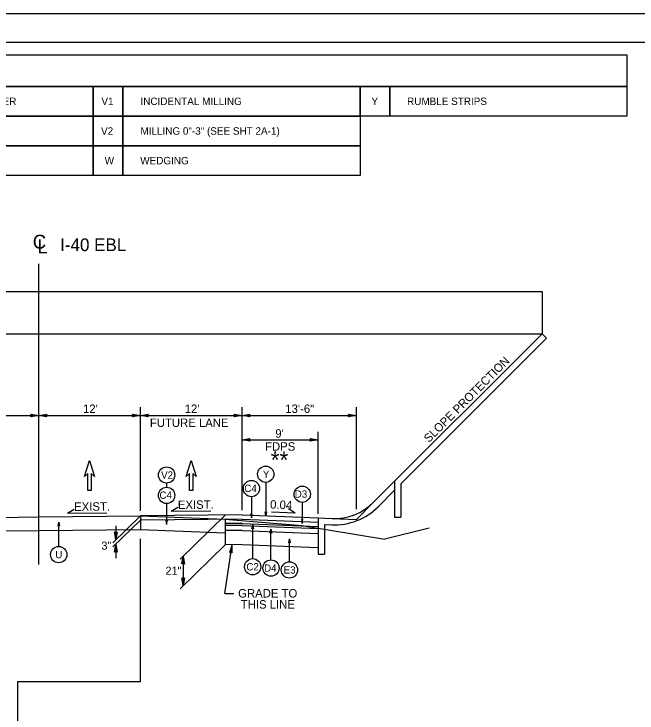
# Model space of a CAD drawing. Extents: x 1553884 to 1554215, y 810431 to 810779.
# Drawn here: x 1554061 to 1554134.5, y 810513.5 to 810596 of the extents above; entities that cross this region are included whole.
import ezdxf

# ---------------------------------------------------------------- set-up
doc = ezdxf.new("R2010")
doc.units = 0
for name, color, linetype in [('Old_Level_15', 7, 'Continuous'), ('Old_Level_2', 7, 'Continuous'), ('Old_Level_20', 7, 'Continuous'), ('P_RDY_Bridge_Abutment', 7, 'Continuous'), ('Prop Dimension', 7, 'Continuous'), ('Prop Hatching', 7, 'Continuous'), ('Prop Lane Arrow CELL', 7, 'Continuous'), ('Prop Shade Light', 7, 'Continuous'), ('Typical Arrow Superelevation CELL', 7, 'Continuous'), ('Typical Detail Pavement Repair CELL', 7, 'Continuous'), ('Typical Shoulder Slope CELL', 7, 'Continuous'), ('Typical Text Centerline CELL', 7, 'Continuous'), ('Typical Text ID Circle CELL', 7, 'Continuous')]:
    doc.layers.add(name, color=color, linetype=linetype)

msp = doc.modelspace()

# ---------------------------------------------------------------- linework, layer by layer
at = {"layer": 'Old_Level_15'}
for points in [[(1554062.95, 810548.722), (1554063.887, 810548.561), (1554062.945, 810548.394), (1554063.064, 810548.561)], [(1554064.825, 810548.4), (1554063.887, 810548.561), (1554064.83, 810548.728), (1554064.71, 810548.561)], [(1554074.95, 810548.722), (1554075.887, 810548.561), (1554074.945, 810548.394), (1554075.064, 810548.561)], [(1554076.825, 810548.4), (1554075.887, 810548.561), (1554076.83, 810548.728), (1554076.71, 810548.561)], [(1554086.95, 810548.722), (1554087.887, 810548.561), (1554086.945, 810548.394), (1554087.064, 810548.561)], [(1554088.825, 810548.4), (1554087.887, 810548.561), (1554088.83, 810548.728), (1554088.71, 810548.561)], [(1554100.45, 810548.722), (1554101.387, 810548.561), (1554100.445, 810548.394), (1554100.564, 810548.561)], [(1554088.825, 810545.538), (1554087.887, 810545.7), (1554088.83, 810545.866), (1554088.71, 810545.7)], [(1554095.95, 810545.861), (1554096.887, 810545.7), (1554095.945, 810545.533), (1554096.064, 810545.7)], [(1554090.767, 810537.19), (1554090.686, 810536.722), (1554090.603, 810537.193), (1554090.686, 810537.133)], [(1554088.925, 810536.968), (1554089.006, 810536.5), (1554089.089, 810536.971), (1554089.006, 810536.911)], [(1554094.916, 810536.298), (1554094.997, 810535.83), (1554095.08, 810536.301), (1554094.997, 810536.241)], [(1554066.169, 810535.51), (1554066.25, 810535.978), (1554066.333, 810535.507), (1554066.25, 810535.567)], [(1554078.908, 810536.163), (1554078.989, 810535.694), (1554079.072, 810536.165), (1554078.989, 810536.106)], [(1554089.065, 810535.208), (1554089.146, 810535.677), (1554089.229, 810535.206), (1554089.146, 810535.266)], [(1554073.15, 810534.815), (1554072.988, 810533.877), (1554072.822, 810534.82), (1554072.988, 810534.7)], [(1554091.229, 810534.689), (1554091.309, 810535.158), (1554091.393, 810534.687), (1554091.309, 810534.747)], [(1554093.409, 810533.556), (1554093.49, 810534.025), (1554093.573, 810533.554), (1554093.49, 810533.614)], [(1554072.827, 810532.44), (1554072.988, 810533.377), (1554073.155, 810532.435), (1554072.988, 810532.554)], [(1554086.738, 810532.371), (1554086.719, 810533.322), (1554086.413, 810532.415), (1554086.596, 810532.509)], [(1554080.787, 810531.044), (1554080.948, 810531.982), (1554081.115, 810531.039), (1554080.948, 810531.159)], [(1554081.11, 810529.419), (1554080.948, 810528.482), (1554080.782, 810529.424), (1554080.948, 810529.304)]]:
    msp.add_lwpolyline(points, close=True, dxfattribs=at)
at = {"layer": 'Old_Level_2'}
msp.add_line((1554154.325, 810592.576), (1553906.825, 810592.576), dxfattribs=at)
at = {"layer": 'Old_Level_20'}
for p, q in [((1554051.887, 810536.474), (1554063.887, 810536.594)), ((1554063.887, 810536.594), (1554075.887, 810536.714)), ((1554075.887, 810536.714), (1554072.651, 810533.548)), ((1554075.887, 810536.214), (1554072.651, 810533.048)), ((1554075.887, 810536.714), (1554085.887, 810536.314)), ((1554075.887, 810536.714), (1554075.887, 810535.129)), ((1554085.887, 810536.814), (1554080.57, 810531.611)), ((1554085.887, 810536.314), (1554085.887, 810534.729)), ((1554085.887, 810536.314), (1554094.933, 810535.59)), ((1554072.988, 810535.544), (1554072.988, 810533.877)), ((1554094.933, 810535.59), (1554104.761, 810533.952)), ((1554051.887, 810534.889), (1554063.887, 810535.009)), ((1554063.887, 810535.009), (1554075.887, 810535.129)), ((1554075.887, 810535.129), (1554085.887, 810534.729)), ((1554109.972, 810535.255), (1554104.761, 810533.952)), ((1554072.988, 810533.377), (1554072.988, 810531.711)), ((1554085.887, 810533.314), (1554080.57, 810528.111)), ((1554080.948, 810531.982), (1554080.948, 810528.482))]:
    msp.add_line(p, q, dxfattribs=at)
at = {"layer": 'P_RDY_Bridge_Abutment'}
for p, q in [((1553919.386, 810563.217), (1554123.308, 810563.217)), ((1554123.308, 810563.217), (1554123.308, 810558.217)), ((1553919.386, 810558.217), (1554123.308, 810558.217)), ((1554103.421, 810538.329), (1554123.308, 810558.217)), ((1554106.637, 810540.485), (1554123.838, 810557.686)), ((1554123.308, 810558.217), (1554123.838, 810557.686)), ((1554105.887, 810540.796), (1554105.887, 810536.554)), ((1554106.637, 810540.485), (1554106.637, 810536.554)), ((1554103.951, 810537.799), (1554105.887, 810539.735)), ((1554101.387, 810536.296), (1554103.421, 810538.329)), ((1554096.887, 810536.474), (1554098.514, 810536.409)), ((1554096.887, 810536.474), (1554096.887, 810532.218)), ((1554098.514, 810536.409), (1554101.387, 810536.296)), ((1554105.887, 810536.554), (1554106.637, 810536.554)), ((1554097.637, 810535.693), (1554098.484, 810535.66)), ((1554097.637, 810535.693), (1554097.637, 810532.218)), ((1554096.887, 810532.218), (1554097.637, 810532.218))]:
    msp.add_line(p, q, dxfattribs=at)
for radius in [6.572, 7.322]:
    msp.add_arc((1554098.773, 810542.976), radius, 267.73793, 315, dxfattribs=at)
at = {"layer": 'Prop Dimension'}
for points in [[(1553912.825, 810591.115), (1554133.325, 810591.115), (1554133.325, 810587.396), (1553912.825, 810587.396)], [(1554042.325, 810587.396), (1554070.325, 810587.396), (1554070.325, 810583.896), (1554042.325, 810583.896)], [(1554070.325, 810587.396), (1554073.825, 810587.396), (1554073.825, 810583.896), (1554070.325, 810583.896)], [(1554070.325, 810587.396), (1554073.825, 810587.396), (1554073.825, 810583.896), (1554070.325, 810583.896)], [(1554073.825, 810587.396), (1554101.825, 810587.396), (1554101.825, 810583.896), (1554073.825, 810583.896)], [(1554101.825, 810587.396), (1554105.325, 810587.396), (1554105.325, 810583.896), (1554101.825, 810583.896)], [(1554101.825, 810587.396), (1554105.325, 810587.396), (1554105.325, 810583.896), (1554101.825, 810583.896)], [(1554105.325, 810587.396), (1554133.325, 810587.396), (1554133.325, 810583.896), (1554105.325, 810583.896)], [(1554042.325, 810583.896), (1554070.325, 810583.896), (1554070.325, 810580.396), (1554042.325, 810580.396)], [(1554070.325, 810583.896), (1554073.825, 810583.896), (1554073.825, 810580.396), (1554070.325, 810580.396)], [(1554073.825, 810583.896), (1554101.825, 810583.896), (1554101.825, 810580.396), (1554073.825, 810580.396)], [(1554042.325, 810580.396), (1554070.325, 810580.396), (1554070.325, 810576.896), (1554042.325, 810576.896)], [(1554070.325, 810580.396), (1554073.825, 810580.396), (1554073.825, 810576.896), (1554070.325, 810576.896)], [(1554073.825, 810580.396), (1554101.825, 810580.396), (1554101.825, 810576.896), (1554073.825, 810576.896)]]:
    msp.add_lwpolyline(points, close=True, dxfattribs=at)
at = {"layer": 'Prop Hatching'}
for p, q in [((1554063.887, 810530.987), (1554063.887, 810566.46)), ((1554075.887, 810517.168), (1554075.887, 810533.991)), ((1554061.417, 810502.52), (1554061.417, 810517.168)), ((1554061.417, 810517.168), (1554075.887, 810517.168))]:
    msp.add_line(p, q, dxfattribs=at)
for points in [[(1554070.481, 810541.354), (1554070.075, 810541.729), (1554070.075, 810539.729), (1554069.7, 810539.729), (1554069.7, 810541.729), (1554069.294, 810541.354), (1554069.887, 810543.26)], [(1554082.481, 810541.354), (1554082.075, 810541.729), (1554082.075, 810539.729), (1554081.7, 810539.729), (1554081.7, 810541.729), (1554081.294, 810541.354), (1554081.887, 810543.26)]]:
    msp.add_lwpolyline(points, close=True, dxfattribs=at)
at = {"layer": 'Prop Lane Arrow CELL'}
msp.add_line((1554156.35, 810595.951), (1553901.353, 810595.951), dxfattribs=at)
at = {"layer": 'Prop Shade Light'}
for p, q in [((1554087.887, 810536.834), (1554075.887, 810536.714)), ((1554087.887, 810536.334), (1554075.887, 810536.214)), ((1554087.887, 810536.834), (1554096.887, 810536.474)), ((1554087.887, 810536.334), (1554096.887, 810535.974)), ((1554087.887, 810535.834), (1554085.887, 810535.814)), ((1554087.887, 810535.584), (1554085.887, 810535.564)), ((1554087.887, 810535.834), (1554096.887, 810535.474)), ((1554087.887, 810535.584), (1554096.887, 810535.224)), ((1554087.887, 810535), (1554085.887, 810534.98)), ((1554085.887, 810534.729), (1554085.887, 810533.314)), ((1554087.887, 810535), (1554096.887, 810534.64)), ((1554087.887, 810533.334), (1554085.887, 810533.314)), ((1554087.887, 810533.334), (1554096.887, 810532.974))]:
    msp.add_line(p, q, dxfattribs=at)
at = {"layer": 'Typical Arrow Superelevation CELL'}
for p, q in [((1554101.387, 810537.498), (1554101.387, 810549.561)), ((1554096.887, 810536.958), (1554096.887, 810546.624)), ((1554067.279, 810537.042), (1554068.066, 810537.507)), ((1554067.279, 810537.042), (1554071.94, 810537.088)), ((1554079.529, 810537.263), (1554080.316, 810537.729)), ((1554079.529, 810537.263), (1554084.19, 810537.31)), ((1554094.168, 810537.051), (1554091.373, 810537.163)), ((1554094.168, 810537.051), (1554093.395, 810537.54)), ((1554085.844, 810527.557), (1554086.719, 810533.322)), ((1554085.844, 810527.557), (1554086.905, 810527.557))]:
    msp.add_line(p, q, dxfattribs=at)
at = {"layer": 'Typical Shoulder Slope CELL'}
for p, q in [((1554075.887, 810537.296), (1554075.887, 810549.561)), ((1554087.887, 810537.397), (1554087.887, 810549.561)), ((1554051.887, 810548.561), (1554063.887, 810548.561)), ((1554063.887, 810548.561), (1554075.887, 810548.561)), ((1554075.887, 810548.561), (1554087.887, 810548.561)), ((1554087.887, 810548.561), (1554101.387, 810548.561)), ((1554087.887, 810545.7), (1554096.887, 810545.7))]:
    msp.add_line(p, q, dxfattribs=at)
at = {"layer": 'Typical Text ID Circle CELL'}
for p, q in [((1554078.989, 810540.58), (1554078.989, 810540.103)), ((1554090.686, 810540.674), (1554090.686, 810536.722)), ((1554089.006, 810538.985), (1554089.006, 810536.5)), ((1554078.989, 810538.18), (1554078.989, 810535.694)), ((1554094.997, 810538.315), (1554094.997, 810535.83)), ((1554066.25, 810533.11), (1554066.25, 810535.978)), ((1554089.146, 810531.669), (1554089.146, 810535.677)), ((1554091.309, 810531.518), (1554091.309, 810535.158)), ((1554093.49, 810531.3), (1554093.49, 810534.025))]:
    msp.add_line(p, q, dxfattribs=at)
for centre in [(1554078.989, 810541.542), (1554090.686, 810541.635), (1554089.006, 810539.946), (1554078.989, 810539.141), (1554094.997, 810539.276), (1554066.25, 810532.149), (1554089.146, 810530.708), (1554091.309, 810530.557), (1554093.49, 810530.339)]:
    msp.add_circle(centre, 0.962, dxfattribs=at)

# ---------------------------------------------------------------- texts
at = {"layer": 'Old_Level_20'}
for s, p in [('3"', (1554071.294, 810532.729)), ('21"', (1554078.855, 810529.764))]:
    msp.add_text(s, height=0.9558, dxfattribs=at).set_placement(p)
at = {"layer": 'Prop Dimension'}
for s, p in [('CONCRETE BARRIER', (1554049.158, 810585.208)), ('V1', (1554071.292, 810585.208)), ('INCIDENTAL MILLING', (1554075.902, 810585.208)), ('Y', (1554103.176, 810585.208)), ('RUMBLE STRIPS', (1554107.376, 810585.208)), ('V2', (1554071.247, 810581.708)), ('MILLING 0"-3" (SEE SHT 2A-1)', (1554075.902, 810581.708)), ('W', (1554071.676, 810578.208)), ('WEDGING', (1554075.876, 810578.208))]:
    msp.add_text(s, height=0.875, dxfattribs=at).set_placement(p)
at = {"layer": 'Typical Arrow Superelevation CELL'}
for s, height, p in [('I-40 EBL', 1.5, (1554066.418, 810567.965)), ("12'", 1, (1554069.119, 810548.861)), ("12'", 1, (1554081.119, 810548.861)), ('13\'-6"', 1, (1554093, 810548.861)), ('FUTURE LANE', 1, (1554077.009, 810547.209)), ("9'", 1, (1554091.817, 810545.948)), ('FDPS', 1, (1554090.607, 810544.41)), ('**', 2, (1554091.275, 810542.325)), ('GRADE TO ', 1, (1554087.432, 810527.084)), ('THIS LINE', 1, (1554087.743, 810525.773))]:
    msp.add_text(s, height=height, dxfattribs=at).set_placement(p)
for s, rotation, p in [('SLOPE PROTECTION', 45, (1554109.947, 810545.297)), ('EXIST.', 0.57294, (1554068.07, 810537.3)), ('EXIST.', 0.57294, (1554080.32, 810537.522)), ('0.04', 357.70939, (1554091.193, 810537.588))]:
    msp.add_text(s, height=1, rotation=rotation, dxfattribs=at).set_placement(p)
at = {"layer": 'Typical Detail Pavement Repair CELL'}
for s, height, p in [('Y', 0.861, (1554090.349, 810541.205)), ('V2', 0.8608, (1554078.338, 810541.108)), ('C4', 0.8608, (1554088.157, 810539.54)), ('C4', 0.8608, (1554078.14, 810538.735)), ('D3', 0.8608, (1554094.113, 810538.87)), ('U', 0.861, (1554065.841, 810531.719)), ('C2', 0.8608, (1554088.403, 810530.277)), ('D4', 0.8608, (1554090.491, 810530.126)), ('E3', 0.8608, (1554092.801, 810529.909))]:
    msp.add_text(s, height=height, dxfattribs=at).set_placement(p)
at = {"layer": 'Typical Text Centerline CELL'}
msp.add_text('C', height=1.64, dxfattribs=at).set_placement((1554063.185, 810568.256))
msp.add_text('L', height=1.641, rotation=359.9469, dxfattribs=at).set_placement((1554063.73, 810567.696))

doc.saveas('drawing.dxf')
